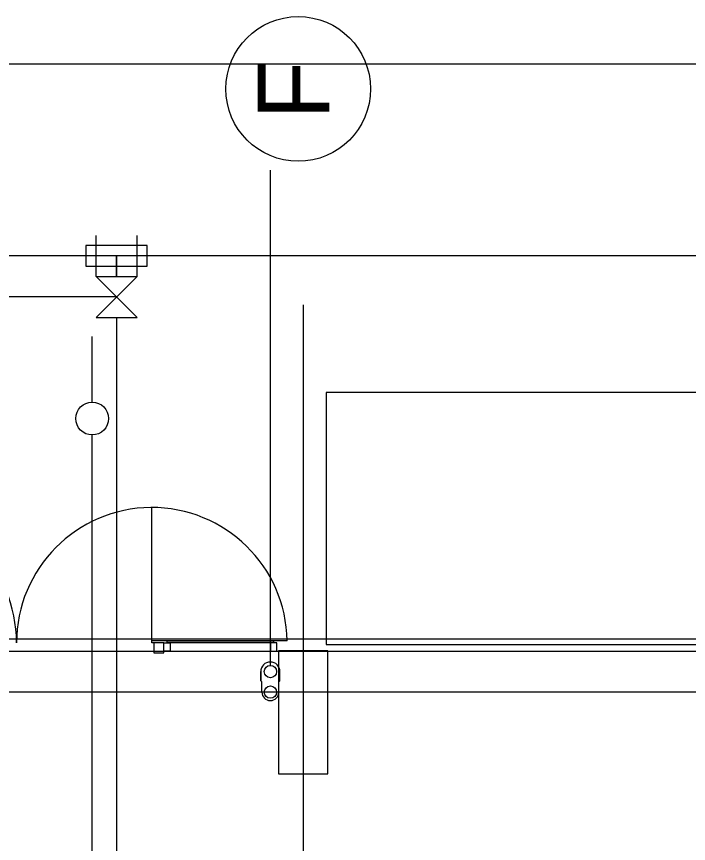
# Model space of a CAD drawing. Extents: x -264222 to -263592, y -1242345 to -1242048.
# Drawn here: x -263887.96 to -263879.77, y -1242089.8 to -1242079.72 of the extents above; entities that cross this region are included whole.
import ezdxf

# ---------------------------------------------------------------- set-up
doc = ezdxf.new("R2010")
doc.units = 0
for name, color, linetype in [('HESCON_OSI_STAVBY_KFA', 7, 'Continuous'), ('KFA_2D_SITUACIA_DSP', 7, 'Continuous'), ('KFA_SO_62-1_VO_TRASA_KABLOV_PROJEKT', 7, 'Continuous')]:
    doc.layers.add(name, color=color, linetype=linetype)

msp = doc.modelspace()

# ---------------------------------------------------------------- linework, layer by layer
at = {"layer": 'HESCON_OSI_STAVBY_KFA'}
for p, q in [((-263884.468, -1242083.237), (-263884.468, -1242083.237)), ((-263884.468, -1242083.237), (-263884.468, -1242246.707)), ((-263792.653, -1242087.957), (-263911.523, -1242087.957))]:
    msp.add_line(p, q, dxfattribs=at)
msp.add_circle((-263884.528, -1242080.605), 0.882, dxfattribs=at)
at = {"layer": 'KFA_2D_SITUACIA_DSP'}
for p, q in [((-263884.868, -1242087.632), (-263884.868, -1242081.594)), ((-263886.993, -1242082.89), (-263886.993, -1242082.39)), ((-263886.493, -1242082.89), (-263886.493, -1242082.39)), ((-263886.368, -1242082.515), (-263887.118, -1242082.515)), ((-263887.118, -1242082.515), (-263887.118, -1242082.765)), ((-263886.368, -1242082.765), (-263886.368, -1242082.515)), ((-263788.143, -1242082.64), (-263924.143, -1242082.64)), ((-263886.743, -1242082.64), (-263886.743, -1242082.89)), ((-263886.743, -1242082.89), (-263886.743, -1242082.64)), ((-263887.118, -1242082.765), (-263886.368, -1242082.765)), ((-263886.993, -1242082.89), (-263886.493, -1242082.89)), ((-263886.493, -1242082.89), (-263886.993, -1242083.39)), ((-263886.493, -1242083.39), (-263886.993, -1242082.89)), ((-263886.743, -1242083.14), (-263888.618, -1242083.14)), ((-263886.993, -1242083.39), (-263886.493, -1242083.39)), ((-263886.743, -1242083.39), (-263886.743, -1242093.007)), ((-263887.041, -1242084.423), (-263887.04, -1242083.623)), ((-263884.188, -1242084.307), (-263884.188, -1242087.377)), ((-263876.738, -1242084.307), (-263884.188, -1242084.307)), ((-263887.043, -1242093.007), (-263887.041, -1242084.823)), ((-263886.313, -1242087.357), (-263886.313, -1242085.707)), ((-263884.663, -1242087.332), (-263886.313, -1242087.332)), ((-263886.288, -1242087.357), (-263886.313, -1242087.357)), ((-263886.288, -1242087.357), (-263886.288, -1242087.477)), ((-263886.168, -1242087.357), (-263886.288, -1242087.357)), ((-263886.168, -1242087.457), (-263886.168, -1242087.357)), ((-263886.168, -1242087.357), (-263886.128, -1242087.357)), ((-263886.168, -1242087.477), (-263886.168, -1242087.357)), ((-263886.128, -1242087.332), (-263884.828, -1242087.332)), ((-263886.128, -1242087.357), (-263886.128, -1242087.332)), ((-263884.828, -1242087.357), (-263886.128, -1242087.357)), ((-263886.128, -1242087.357), (-263886.088, -1242087.357)), ((-263886.088, -1242087.357), (-263886.088, -1242087.457)), ((-263884.828, -1242087.357), (-263884.868, -1242087.357)), ((-263884.868, -1242087.357), (-263884.868, -1242087.457)), ((-263884.828, -1242087.332), (-263884.828, -1242087.357)), ((-263884.788, -1242087.357), (-263884.828, -1242087.357)), ((-263884.788, -1242087.457), (-263884.788, -1242087.357)), ((-263884.188, -1242087.377), (-263876.738, -1242087.377)), ((-263894.581, -1242087.457), (-263809.355, -1242087.457)), ((-263886.288, -1242087.477), (-263886.168, -1242087.477)), ((-263886.088, -1242087.457), (-263886.168, -1242087.457)), ((-263884.868, -1242087.457), (-263884.788, -1242087.457)), ((-263884.168, -1242087.452), (-263884.768, -1242087.452)), ((-263884.768, -1242087.452), (-263884.768, -1242088.952)), ((-263884.168, -1242088.952), (-263884.168, -1242087.452)), ((-263884.985, -1242087.707), (-263884.985, -1242087.818)), ((-263884.985, -1242087.818), (-263884.985, -1242087.707)), ((-263884.751, -1242087.818), (-263884.751, -1242087.707)), ((-263884.971, -1242087.832), (-263884.985, -1242087.818)), ((-263884.971, -1242087.957), (-263884.971, -1242087.832)), ((-263884.765, -1242087.832), (-263884.751, -1242087.818)), ((-263884.765, -1242087.957), (-263884.765, -1242087.832)), ((-263884.768, -1242088.952), (-263884.168, -1242088.952))]:
    msp.add_line(p, q, dxfattribs=at)
msp.add_lwpolyline([(-263794.893, -1242227.382), (-263808.968, -1242241.457), (-263894.968, -1242241.457), (-263909.043, -1242227.382), (-263909.043, -1242196.333), (-263914.143, -1242196.333), (-263914.143, -1242132.433), (-263909.043, -1242132.433), (-263909.043, -1242101.382), (-263894.968, -1242087.307), (-263808.968, -1242087.307), (-263794.893, -1242101.382), (-263794.893, -1242227.382)], dxfattribs=at)
for centre, radius in [((-263887.04, -1242084.623), 0.2), ((-263884.868, -1242087.707), 0.075), ((-263884.868, -1242087.957), 0.075)]:
    msp.add_circle(centre, radius, dxfattribs=at)
for centre, radius, start, end in [((-263889.613, -1242087.357), 1.65, 0, 179.1318), ((-263886.313, -1242087.357), 1.65, 0.8682, 180), ((-263884.868, -1242087.707), 0.117, 0, 180), ((-263884.868, -1242087.957), 0.103, 180, 0)]:
    msp.add_arc(centre, radius, start, end, dxfattribs=at)
at = {"layer": 'KFA_SO_62-1_VO_TRASA_KABLOV_PROJEKT'}
msp.add_line((-263876.274, -1242080.304), (-263895.58, -1242080.304), dxfattribs=at)

# ---------------------------------------------------------------- texts
at = {"layer": 'HESCON_OSI_STAVBY_KFA'}
msp.add_text('F', height=0.875, rotation=90, dxfattribs=at).set_placement((-263884.147, -1242080.978))

doc.saveas('drawing.dxf')
